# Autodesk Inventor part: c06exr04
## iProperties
Shininess: 77.0
Length Units: 11269
Angle Units: 11279
Time Units: 11290
Mass Units: 11283
Length Display Precision: 3
Angle Display Precision: 2
Created: 2001-12
Part Number: c06exr04
Document SubType Name: Modeling
Density: 1 g/cm^3
Density: 0.0
Volumn: 0.0
Area: 0.0
PropertySet Name: Model Information
Control State: 0
Master: False
Checked Out: False
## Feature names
1. Extrusion1
2. Extrusion2
3. Extrusion3
4. Extrusion4
5. Extrusion5
6. Extrusion6
7. Hole1
8. Hole2
9. Hole3
